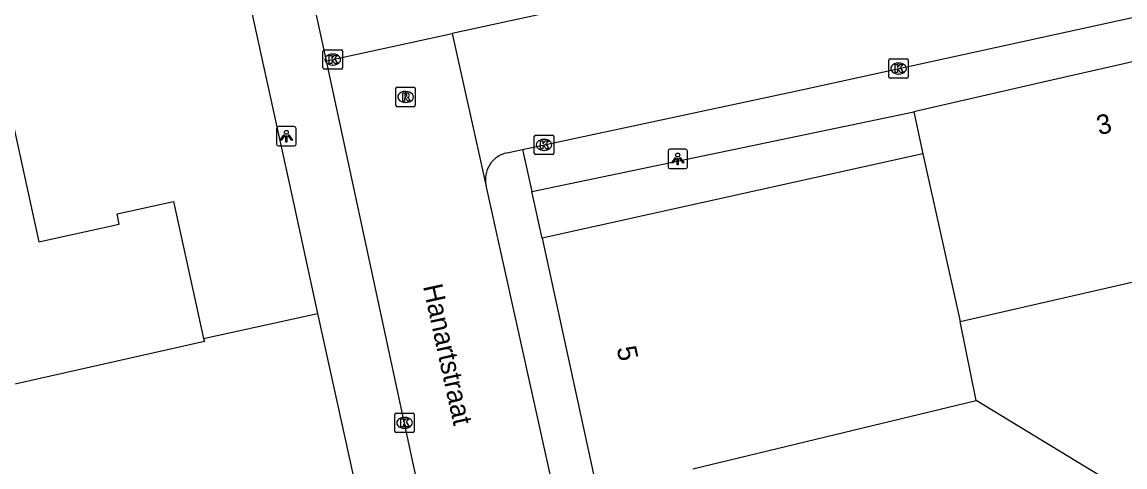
# Model space of a CAD drawing. Extents: x 160557 to 161245, y 385330 to 386505.
# Drawn here: x 160780.5 to 160836.9, y 385840.7 to 385863.5 of the extents above; entities that cross this region are included whole.
import ezdxf

# ---------------------------------------------------------------- set-up
doc = ezdxf.new("R2010")
doc.units = 0
for name, color, linetype in [('IMGEO_Kolk', 7, 'Continuous'), ('IMGEO_Lichtpunt', 7, 'Continuous'), ('IMGEO_Openbare_ruimte_label', 7, 'Continuous'), ('IMGEO_Pand', 7, 'Continuous'), ('IMGEO_Pand_nummerreeks', 7, 'Continuous'), ('IMGEO_Parkeervlak_open', 7, 'Continuous'), ('IMGEO_Rijbaan_lokaal_open', 7, 'Continuous'), ('IMGEO_Rioolput', 7, 'Continuous')]:
    doc.layers.add(name, color=color, linetype=linetype)

msp = doc.modelspace()

# ---------------------------------------------------------------- linework, layer by layer
at = {"layer": 'IMGEO_Kolk'}
for p, q in [((160795.886, 385861.122), (160795.886, 385861.974)), ((160795.961, 385862.048), (160796.813, 385862.048)), ((160796.887, 385861.974), (160796.887, 385861.122)), ((160796.374, 385861.828), (160796.399, 385861.828)), ((160824.839, 385860.661), (160824.839, 385861.513)), ((160824.914, 385861.587), (160825.766, 385861.587)), ((160825.84, 385861.513), (160825.84, 385860.661)), ((160796.813, 385861.048), (160795.961, 385861.048)), ((160796.397, 385861.268), (160796.372, 385861.268)), ((160825.35, 385860.807), (160825.325, 385860.807)), ((160825.327, 385861.367), (160825.352, 385861.367)), ((160825.766, 385860.587), (160824.914, 385860.587)), ((160806.699, 385856.751), (160806.699, 385857.603)), ((160806.774, 385857.677), (160807.626, 385857.677)), ((160807.187, 385857.457), (160807.212, 385857.457)), ((160807.7, 385857.603), (160807.7, 385856.751)), ((160807.21, 385856.897), (160807.185, 385856.897)), ((160807.626, 385856.677), (160806.774, 385856.677)), ((160799.557, 385842.51), (160799.557, 385843.362)), ((160799.632, 385843.436), (160800.484, 385843.436)), ((160800.558, 385843.362), (160800.558, 385842.51)), ((160800.045, 385843.216), (160800.07, 385843.216)), ((160800.484, 385842.436), (160799.632, 385842.436)), ((160800.068, 385842.656), (160800.043, 385842.656))]:
    msp.add_line(p, q, dxfattribs=at)
for points in [[(160795.886, 385861.122), (160795.886, 385861.974)], [(160795.961, 385862.048), (160796.813, 385862.048)], [(160796.887, 385861.974), (160796.887, 385861.122)], [(160796.207, 385861.748), (160796.33, 385861.748), (160796.33, 385861.597), (160796.46, 385861.748), (160796.624, 385861.748), (160796.478, 385861.597), (160796.631, 385861.348), (160796.479, 385861.348), (160796.394, 385861.512), (160796.33, 385861.445), (160796.33, 385861.348), (160796.207, 385861.348), (160796.207, 385861.748)], [(160824.839, 385860.661), (160824.839, 385861.513)], [(160824.914, 385861.587), (160825.766, 385861.587)], [(160825.84, 385861.513), (160825.84, 385860.661)], [(160796.813, 385861.048), (160795.961, 385861.048)], [(160825.16, 385861.287), (160825.283, 385861.287), (160825.283, 385861.136), (160825.413, 385861.287), (160825.577, 385861.287), (160825.431, 385861.136), (160825.584, 385860.887), (160825.432, 385860.887), (160825.347, 385861.051), (160825.283, 385860.984), (160825.283, 385860.887), (160825.16, 385860.887), (160825.16, 385861.287)], [(160825.766, 385860.587), (160824.914, 385860.587)], [(160806.699, 385856.751), (160806.699, 385857.603)], [(160806.774, 385857.677), (160807.626, 385857.677)], [(160807.7, 385857.603), (160807.7, 385856.751)], [(160807.02, 385857.377), (160807.143, 385857.377), (160807.143, 385857.226), (160807.273, 385857.377), (160807.437, 385857.377), (160807.291, 385857.226), (160807.444, 385856.977), (160807.292, 385856.977), (160807.207, 385857.141), (160807.143, 385857.074), (160807.143, 385856.977), (160807.02, 385856.977), (160807.02, 385857.377)], [(160807.626, 385856.677), (160806.774, 385856.677)], [(160799.557, 385842.51), (160799.557, 385843.362)], [(160799.632, 385843.436), (160800.484, 385843.436)], [(160800.558, 385843.362), (160800.558, 385842.51)], [(160799.878, 385843.136), (160800.001, 385843.136), (160800.001, 385842.985), (160800.131, 385843.136), (160800.295, 385843.136), (160800.149, 385842.985), (160800.302, 385842.736), (160800.15, 385842.736), (160800.065, 385842.9), (160800.001, 385842.833), (160800.001, 385842.736), (160799.878, 385842.736), (160799.878, 385843.136)], [(160800.484, 385842.436), (160799.632, 385842.436)]]:
    msp.add_lwpolyline(points, dxfattribs=at)
for centre, start, end in [((160795.963, 385861.972), 91.552, 178.448), ((160795.963, 385861.972), 91.552, 178.448), ((160796.811, 385861.972), 1.552, 88.448), ((160796.811, 385861.972), 1.552, 88.448), ((160824.916, 385861.511), 91.552, 178.448), ((160824.916, 385861.511), 91.552, 178.448), ((160825.764, 385861.511), 1.552, 88.448), ((160825.764, 385861.511), 1.552, 88.448), ((160795.963, 385861.124), 181.552, 268.448), ((160795.963, 385861.124), 181.552, 268.448), ((160796.811, 385861.124), 271.552, 358.448), ((160796.811, 385861.124), 271.552, 358.448), ((160824.916, 385860.663), 181.552, 268.448), ((160824.916, 385860.663), 181.552, 268.448), ((160825.764, 385860.663), 271.552, 358.448), ((160825.764, 385860.663), 271.552, 358.448), ((160806.776, 385857.601), 91.552, 178.448), ((160806.776, 385857.601), 91.552, 178.448), ((160807.624, 385857.601), 1.552, 88.448), ((160807.624, 385857.601), 1.552, 88.448), ((160806.776, 385856.753), 181.552, 268.448), ((160806.776, 385856.753), 181.552, 268.448), ((160807.624, 385856.753), 271.552, 358.448), ((160807.624, 385856.753), 271.552, 358.448), ((160799.634, 385843.36), 91.552, 178.448), ((160799.634, 385843.36), 91.552, 178.448), ((160800.482, 385843.36), 1.552, 88.448), ((160800.482, 385843.36), 1.552, 88.448), ((160799.634, 385842.512), 181.552, 268.448), ((160799.634, 385842.512), 181.552, 268.448), ((160800.482, 385842.512), 271.552, 358.448), ((160800.482, 385842.512), 271.552, 358.448)]:
    msp.add_arc(centre, 0.0765, start, end, dxfattribs=at)
for centre, major_axis, ratio, start_param, end_param in [((160796.373, 385861.548), (-0.387, 0.002), 0.722429, 4.712389, 7.853982), ((160796.398, 385861.548), (-0.39, 0.002), 0.717154, 1.570796, 4.712389), ((160825.326, 385861.087), (-0.387, 0.002), 0.722429, 4.712389, 7.853982), ((160825.351, 385861.087), (-0.39, 0.002), 0.717154, 1.570796, 4.712389), ((160807.186, 385857.177), (-0.387, 0.002), 0.722429, 4.712389, 7.853982), ((160807.211, 385857.177), (-0.39, 0.002), 0.717154, 1.570796, 4.712389), ((160800.044, 385842.936), (-0.387, 0.002), 0.722429, 4.712389, 7.853982), ((160800.069, 385842.936), (-0.39, 0.002), 0.717154, 1.570796, 4.712389)]:
    msp.add_ellipse(centre, major_axis=major_axis, ratio=ratio, start_param=start_param, end_param=end_param, dxfattribs=at)
at = {"layer": 'IMGEO_Lichtpunt'}
for p, q in [((160793.513, 385858.022), (160793.513, 385857.215)), ((160793.513, 385858.022), (160793.513, 385857.215)), ((160794.415, 385858.117), (160793.607, 385858.117)), ((160794.415, 385858.117), (160793.607, 385858.117)), ((160794.509, 385857.215), (160794.509, 385858.022)), ((160794.509, 385857.215), (160794.509, 385858.022)), ((160793.607, 385857.121), (160794.415, 385857.121)), ((160793.607, 385857.121), (160794.415, 385857.121)), ((160813.544, 385856.86), (160813.544, 385856.053)), ((160813.544, 385856.86), (160813.544, 385856.053)), ((160814.446, 385856.955), (160813.638, 385856.955)), ((160814.446, 385856.955), (160813.638, 385856.955)), ((160814.54, 385856.053), (160814.54, 385856.86)), ((160814.54, 385856.053), (160814.54, 385856.86)), ((160813.638, 385855.959), (160814.446, 385855.959)), ((160813.638, 385855.959), (160814.446, 385855.959))]:
    msp.add_line(p, q, dxfattribs=at)
for points in [[(160793.887, 385857.686), (160793.926, 385857.658), (160793.738, 385857.396), (160793.7, 385857.423), (160793.887, 385857.686)], [(160793.989, 385857.638), (160794.036, 385857.638), (160794.036, 385857.316), (160793.989, 385857.316), (160793.989, 385857.638)], [(160794.099, 385857.658), (160794.137, 385857.685), (160794.324, 385857.423), (160794.285, 385857.395), (160794.099, 385857.658)], [(160813.918, 385856.524), (160813.957, 385856.496), (160813.769, 385856.234), (160813.731, 385856.261), (160813.918, 385856.524)], [(160814.02, 385856.476), (160814.067, 385856.476), (160814.067, 385856.154), (160814.02, 385856.154), (160814.02, 385856.476)], [(160814.13, 385856.496), (160814.168, 385856.523), (160814.355, 385856.261), (160814.316, 385856.233), (160814.13, 385856.496)]]:
    msp.add_lwpolyline(points, dxfattribs=at)
for centre in [(160794.012, 385857.82), (160814.043, 385856.658)]:
    msp.add_circle(centre, 0.0994, dxfattribs=at)
for centre, start, end in [((160793.607, 385858.022), 90, 180), ((160793.607, 385858.022), 90, 180), ((160794.415, 385858.022), 0, 90), ((160794.415, 385858.022), 0, 90), ((160793.607, 385857.215), 180, 270), ((160793.607, 385857.215), 180, 270), ((160794.415, 385857.215), 270, 0), ((160794.415, 385857.215), 270, 360), ((160813.638, 385856.86), 90, 180), ((160813.638, 385856.86), 90, 180), ((160814.446, 385856.86), 0, 90), ((160814.446, 385856.86), 0, 90), ((160813.638, 385856.053), 180, 270), ((160813.638, 385856.053), 180, 270), ((160814.446, 385856.053), 270, 0), ((160814.446, 385856.053), 270, 360)]:
    msp.add_arc(centre, 0.0946, start, end, dxfattribs=at)
at = {"layer": 'IMGEO_Pand'}
for points in [[(160844.138, 385862.995), (160836.876, 385861.33), (160833.192, 385860.485), (160826.13, 385858.866)], [(160828.488, 385848.132), (160844.796, 385851.869), (160846.169, 385854.175), (160844.138, 385862.995)], [(160779.843, 385859.099), (160781.346, 385852.214), (160785.461, 385853.115), (160785.345, 385853.643), (160788.241, 385854.277), (160789.778, 385847.261)], [(160826.13, 385858.866), (160826.584, 385856.714)], [(160826.584, 385856.714), (160807.109, 385852.398)], [(160826.584, 385856.714), (160828.488, 385848.132)], [(160807.109, 385852.398), (160809.898, 385839.522)], [(160789.778, 385847.261), (160795.61, 385848.538)], [(160795.61, 385848.538), (160795.644, 385848.382), (160797.582, 385839.533)], [(160829.322, 385844.074), (160828.488, 385848.132)], [(160789.778, 385847.261), (160789.816, 385847.106), (160761.698, 385840.764)], [(160814.805, 385840.585), (160829.322, 385844.074)], [(160835.706, 385840.185), (160829.322, 385844.074)]]:
    msp.add_lwpolyline(points, dxfattribs=at)
at = {"layer": 'IMGEO_Parkeervlak_open'}
for points in [[(160796.064, 385861.476), (160795.385, 385864.625)], [(160792.241, 385863.947), (160792.688, 385861.904), (160794.287, 385854.597), (160795.61, 385848.538)], [(160806.576, 385854.787), (160826.13, 385858.866)], [(160806.095, 385856.942), (160806.576, 385854.787)], [(160807.109, 385852.398), (160806.576, 385854.787)]]:
    msp.add_lwpolyline(points, dxfattribs=at)
at = {"layer": 'IMGEO_Rijbaan_lokaal_open'}
for points in [[(160855.448, 385874.495), (160842.527, 385871.618), (160823.141, 385867.378), (160802.504, 385862.88)], [(160806.095, 385856.942), (160820.371, 385859.999), (160849.724, 385866.434), (160856.882, 385867.979)], [(160796.064, 385861.476), (160802.504, 385862.88)], [(160802.504, 385862.88), (160804.222, 385855.128), (160804.23, 385855.101)], [(160808.431, 385804.793), (160800.508, 385840.854), (160796.064, 385861.476)], [(160805.303, 385856.772), (160806.095, 385856.942)], [(160815.123, 385806.338), (160809.958, 385829.285), (160804.23, 385855.101)]]:
    msp.add_lwpolyline(points, dxfattribs=at)
msp.add_arc((160805.597, 385855.403), 1.4, 102.1085, 192.48, dxfattribs=at)
at = {"layer": 'IMGEO_Rioolput'}
for p, q in [((160799.61, 385859.207), (160799.61, 385860.059)), ((160799.685, 385860.133), (160800.537, 385860.133)), ((160800.098, 385859.913), (160800.123, 385859.913)), ((160800.611, 385860.059), (160800.611, 385859.207)), ((160800.537, 385859.133), (160799.685, 385859.133)), ((160800.121, 385859.353), (160800.096, 385859.353))]:
    msp.add_line(p, q, dxfattribs=at)
for points in [[(160799.61, 385859.207), (160799.61, 385860.059)], [(160799.685, 385860.133), (160800.537, 385860.133)], [(160800.199, 385859.831), (160799.947, 385859.833), (160799.947, 385859.433)], [(160800.125, 385859.752), (160800.071, 385859.752), (160800.071, 385859.671)], [(160800.611, 385860.059), (160800.611, 385859.207)], [(160800.537, 385859.133), (160799.685, 385859.133)], [(160799.947, 385859.433), (160800.071, 385859.433), (160800.071, 385859.595), (160800.082, 385859.595)], [(160800.071, 385859.671), (160800.123, 385859.671)], [(160800.129, 385859.566), (160800.2, 385859.433), (160800.34, 385859.433), (160800.275, 385859.559)]]:
    msp.add_lwpolyline(points, dxfattribs=at)
for centre, radius, start, end in [((160799.687, 385860.057), 0.0765, 91.552, 178.448), ((160799.687, 385860.057), 0.0765, 91.552, 178.448), ((160800.131, 385859.656), 0.0964, 77.0061, 93.1865), ((160800.145, 385859.713), 0.0378, 276.6634, 79.6772), ((160800.198, 385859.721), 0.109, 350.3612, 89.416), ((160800.196, 385859.721), 0.112, 277.5842, 350.9817), ((160800.535, 385860.057), 0.0765, 1.552, 88.448), ((160800.535, 385860.057), 0.0765, 1.552, 88.448), ((160799.687, 385859.209), 0.0765, 181.552, 268.448), ((160799.687, 385859.209), 0.0765, 181.552, 268.448), ((160800.081, 385859.542), 0.0533, 26.0293, 88.6989), ((160800.107, 385859.86), 0.19, 274.7715, 282.9687), ((160800.18, 385859.506), 0.108, 29.5134, 73.7905), ((160800.535, 385859.209), 0.0765, 271.552, 358.448), ((160800.535, 385859.209), 0.0765, 271.552, 358.448)]:
    msp.add_arc(centre, radius, start, end, dxfattribs=at)
for centre, major_axis, ratio, start_param, end_param in [((160800.097, 385859.633), (-0.387, 0.002), 0.722429, 4.712389, 7.853982), ((160800.122, 385859.633), (-0.39, 0.002), 0.717154, 1.570796, 4.712389)]:
    msp.add_ellipse(centre, major_axis=major_axis, ratio=ratio, start_param=start_param, end_param=end_param, dxfattribs=at)

# ---------------------------------------------------------------- texts
at = {"layer": 'IMGEO_Openbare_ruimte_label'}
msp.add_text('Hanartstraat', height=1, rotation=282.4108, dxfattribs=at).set_placement((160800.999, 385849.935))
at = {"layer": 'IMGEO_Pand_nummerreeks'}
for s, rotation, p in [('3', 12.914, (160835.599, 385857.672)), ('5', 282.2217, (160810.908, 385846.763))]:
    msp.add_text(s, height=1, rotation=rotation, dxfattribs=at).set_placement(p)

doc.saveas('drawing.dxf')
